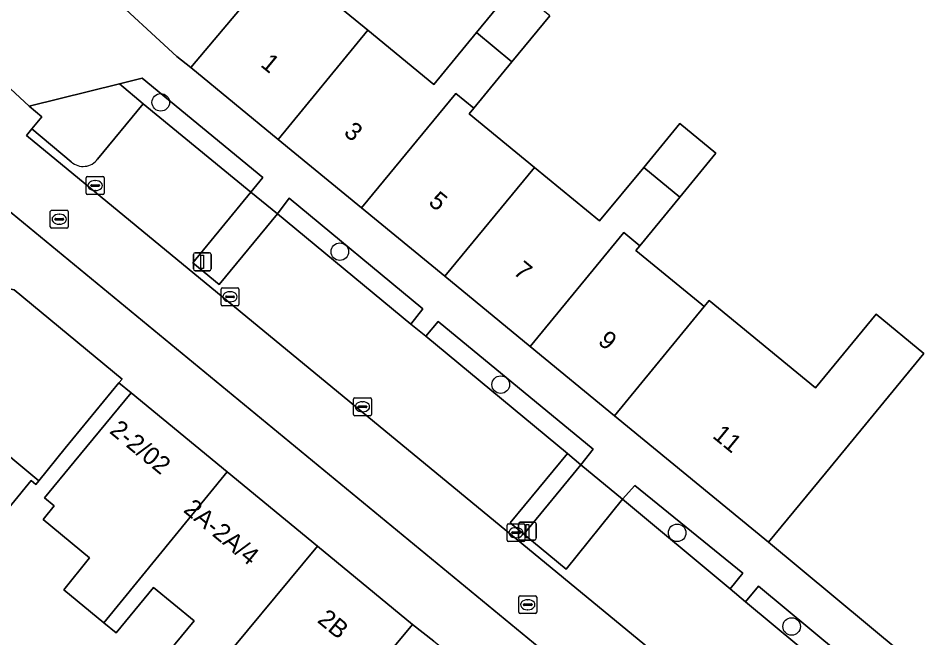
# Model space of a CAD drawing. Extents: x 160157 to 160921, y 381516 to 382045.
# Drawn here: x 160314.8 to 160365.5, y 381930.5 to 381965.1 of the extents above; entities that cross this region are included whole.
import ezdxf

# ---------------------------------------------------------------- set-up
doc = ezdxf.new("R2010")
doc.units = 0
for name, color, linetype in [('IMGEO_Boom', 7, 'Continuous'), ('IMGEO_Erf', 7, 'Continuous'), ('IMGEO_Groenvoorziening', 7, 'Continuous'), ('IMGEO_Haag', 7, 'Continuous'), ('IMGEO_Kolk', 7, 'Continuous'), ('IMGEO_Lichtmast', 7, 'Continuous'), ('IMGEO_Pand', 7, 'Continuous'), ('IMGEO_Pand_nummerreeks', 7, 'Continuous'), ('IMGEO_Parkeervlak_open', 7, 'Continuous'), ('IMGEO_Rijbaan_lokaal_open', 7, 'Continuous'), ('IMGEO_Rioolput', 7, 'Continuous'), ('IMGEO_Voetpad_open', 7, 'Continuous')]:
    doc.layers.add(name, color=color, linetype=linetype)

msp = doc.modelspace()

# ---------------------------------------------------------------- linework, layer by layer
at = {"layer": 'IMGEO_Boom'}
for centre in [(160322.726, 381960.375), (160332.708, 381952.049), (160341.678, 381944.633), (160351.512, 381936.365), (160357.891, 381931.142)]:
    msp.add_circle(centre, 0.489, dxfattribs=at)
at = {"layer": 'IMGEO_Erf'}
for points in [[(160319.596, 381966.674), (160323.63, 381962.943), (160324.402, 381962.313), (160331.716, 381971.016)], [(160331.553, 381966.639), (160334.273, 381964.402), (160337.947, 381961.381), (160340.324, 381964.272), (160342.433, 381966.836)], [(160344.409, 381965.211), (160342.3, 381962.646), (160340.171, 381960.057), (160339.912, 381959.742), (160343.551, 381956.749), (160347.187, 381953.76), (160349.646, 381956.751), (160351.654, 381959.193), (160353.667, 381957.538), (160351.659, 381955.096), (160349.425, 381952.38), (160349.212, 381952.121), (160352.884, 381949.102), (160353.024, 381948.987), (160353.303, 381949.327), (160356.629, 381946.593), (160359.23, 381944.455), (160362.603, 381948.557), (160365.262, 381946.365), (160359.777, 381939.701), (160356.601, 381935.838), (160365.87, 381928.117)], [(160323.177, 381929.746), (160324.583, 381931.452), (160322.328, 381933.31), (160320.241, 381930.777), (160319.551, 381931.345), (160317.331, 381933.175), (160318.753, 381934.963), (160316.167, 381937.112), (160316.789, 381937.866), (160316.242, 381938.317), (160317.893, 381940.32), (160321.073, 381944.178), (160320.396, 381944.729), (160317.394, 381941.086), (160315.932, 381939.263), (160315.768, 381939.058), (160315.504, 381939.276), (160313.335, 381936.645)], [(160337.94, 381930.325), (160336.75, 381931.258), (160333.571, 381927.4)]]:
    msp.add_lwpolyline(points, dxfattribs=at)
at = {"layer": 'IMGEO_Groenvoorziening'}
for points in [[(160321.685, 381961.718), (160320.432, 381961.41), (160321.749, 381960.287), (160327.742, 381955.36), (160328.425, 381956.194)], [(160329.878, 381955.035), (160329.226, 381954.16), (160336.672, 381947.995), (160337.343, 381948.854)], [(160338.181, 381948.144), (160337.502, 381947.343), (160345.394, 381940.788), (160346.146, 381940.163), (160346.828, 381941.024)], [(160349.158, 381939.008), (160348.464, 381938.24), (160354.461, 381933.234), (160355.173, 381934.108)], [(160356.044, 381933.38), (160355.318, 381932.519), (160361.259, 381927.56), (160361.986, 381928.441)]]:
    msp.add_lwpolyline(points, close=True, dxfattribs=at)
for points in [[(160321.749, 381960.287), (160320.432, 381961.41), (160315.4, 381960.173), (160316.098, 381959.567), (160315.541, 381958.892), (160317.74, 381957.054)], [(160319.205, 381957.216), (160321.749, 381960.287)]]:
    msp.add_lwpolyline(points, dxfattribs=at)
msp.add_arc((160318.4, 381957.795), 0.992, 228.3207, 324.2996, dxfattribs=at)
at = {"layer": 'IMGEO_Haag'}
for points in [[(160329.226, 381954.16), (160336.672, 381947.995), (160337.343, 381948.854), (160329.878, 381955.035)], [(160338.181, 381948.144), (160337.502, 381947.343), (160345.394, 381940.788), (160346.146, 381940.163), (160346.828, 381941.024)], [(160354.461, 381933.234), (160355.173, 381934.108), (160349.158, 381939.008), (160348.464, 381938.24)], [(160361.259, 381927.56), (160361.986, 381928.441), (160356.044, 381933.38), (160355.318, 381932.519)]]:
    msp.add_lwpolyline(points, close=True, dxfattribs=at)
at = {"layer": 'IMGEO_Kolk'}
for p, q in [((160318.57, 381955.31), (160318.57, 381956.162)), ((160318.645, 381956.236), (160319.497, 381956.236)), ((160319.058, 381956.016), (160319.083, 381956.016)), ((160319.571, 381956.162), (160319.571, 381955.31)), ((160318.829, 381955.73), (160318.829, 381955.742)), ((160319.267, 381955.693), (160318.869, 381955.693)), ((160318.872, 381955.779), (160319.27, 381955.779)), ((160319.081, 381955.456), (160319.056, 381955.456)), ((160319.313, 381955.742), (160319.313, 381955.73)), ((160319.497, 381955.236), (160318.645, 381955.236)), ((160326.085, 381949.105), (160326.085, 381949.957)), ((160326.16, 381950.031), (160327.012, 381950.031)), ((160327.086, 381949.957), (160327.086, 381949.105)), ((160326.344, 381949.525), (160326.344, 381949.537)), ((160326.782, 381949.488), (160326.384, 381949.488)), ((160326.387, 381949.574), (160326.785, 381949.574)), ((160326.573, 381949.811), (160326.598, 381949.811)), ((160326.828, 381949.537), (160326.828, 381949.525)), ((160327.012, 381949.031), (160326.16, 381949.031)), ((160326.596, 381949.251), (160326.571, 381949.251)), ((160333.468, 381942.971), (160333.468, 381943.823)), ((160333.543, 381943.897), (160334.395, 381943.897)), ((160334.469, 381943.823), (160334.469, 381942.971)), ((160333.727, 381943.391), (160333.727, 381943.403)), ((160334.165, 381943.354), (160333.767, 381943.354)), ((160333.77, 381943.44), (160334.168, 381943.44)), ((160333.956, 381943.677), (160333.981, 381943.677)), ((160334.211, 381943.403), (160334.211, 381943.391)), ((160334.395, 381942.897), (160333.543, 381942.897)), ((160333.979, 381943.117), (160333.954, 381943.117)), ((160342.029, 381935.946), (160342.029, 381936.798)), ((160342.104, 381936.872), (160342.956, 381936.872)), ((160343.03, 381936.798), (160343.03, 381935.946)), ((160342.288, 381936.366), (160342.288, 381936.378)), ((160342.726, 381936.329), (160342.328, 381936.329)), ((160342.331, 381936.415), (160342.729, 381936.415)), ((160342.517, 381936.652), (160342.542, 381936.652)), ((160342.772, 381936.378), (160342.772, 381936.366)), ((160342.956, 381935.872), (160342.104, 381935.872)), ((160342.54, 381936.092), (160342.515, 381936.092))]:
    msp.add_line(p, q, dxfattribs=at)
for points in [[(160318.57, 381955.31), (160318.57, 381956.162)], [(160318.645, 381956.236), (160319.497, 381956.236)], [(160319.571, 381956.162), (160319.571, 381955.31)], [(160319.497, 381955.236), (160318.645, 381955.236)], [(160326.085, 381949.105), (160326.085, 381949.957)], [(160326.16, 381950.031), (160327.012, 381950.031)], [(160327.086, 381949.957), (160327.086, 381949.105)], [(160327.012, 381949.031), (160326.16, 381949.031)], [(160333.468, 381942.971), (160333.468, 381943.823)], [(160333.543, 381943.897), (160334.395, 381943.897)], [(160334.469, 381943.823), (160334.469, 381942.971)], [(160334.395, 381942.897), (160333.543, 381942.897)], [(160342.029, 381935.946), (160342.029, 381936.798)], [(160342.104, 381936.872), (160342.956, 381936.872)], [(160343.03, 381936.798), (160343.03, 381935.946)], [(160342.956, 381935.872), (160342.104, 381935.872)]]:
    msp.add_lwpolyline(points, dxfattribs=at)
for centre, radius, start, end in [((160318.647, 381956.16), 0.0765, 91.552, 178.448), ((160318.647, 381956.16), 0.0765, 91.552, 178.448), ((160319.495, 381956.16), 0.0765, 1.552, 88.448), ((160319.495, 381956.16), 0.0765, 1.552, 88.448), ((160318.869, 381955.739), 0.0403, 85.8775, 175.7526), ((160318.866, 381955.729), 0.0366, 178.938, 274.7102), ((160319.27, 381955.736), 0.043, 264.8664, 352.4533), ((160319.274, 381955.741), 0.0386, 1.7309, 96.639), ((160318.647, 381955.312), 0.0765, 181.552, 268.448), ((160318.647, 381955.312), 0.0765, 181.552, 268.448), ((160319.495, 381955.312), 0.0765, 271.552, 358.448), ((160319.495, 381955.312), 0.0765, 271.552, 358.448), ((160326.162, 381949.955), 0.0765, 91.552, 178.448), ((160326.162, 381949.955), 0.0765, 91.552, 178.448), ((160327.01, 381949.955), 0.0765, 1.552, 88.448), ((160327.01, 381949.955), 0.0765, 1.552, 88.448), ((160326.384, 381949.534), 0.0403, 85.8775, 175.7526), ((160326.381, 381949.524), 0.0366, 178.938, 274.7102), ((160326.785, 381949.531), 0.043, 264.8664, 352.4533), ((160326.789, 381949.536), 0.0386, 1.7309, 96.639), ((160326.162, 381949.107), 0.0765, 181.552, 268.448), ((160326.162, 381949.107), 0.0765, 181.552, 268.448), ((160327.01, 381949.107), 0.0765, 271.552, 358.448), ((160327.01, 381949.107), 0.0765, 271.552, 358.448), ((160333.545, 381943.821), 0.0765, 91.552, 178.448), ((160333.545, 381943.821), 0.0765, 91.552, 178.448), ((160334.393, 381943.821), 0.0765, 1.552, 88.448), ((160334.393, 381943.821), 0.0765, 1.552, 88.448), ((160333.767, 381943.4), 0.0403, 85.8775, 175.7526), ((160333.764, 381943.39), 0.0366, 178.938, 274.7102), ((160334.168, 381943.397), 0.043, 264.8664, 352.4533), ((160334.172, 381943.402), 0.0386, 1.7309, 96.639), ((160333.545, 381942.973), 0.0765, 181.552, 268.448), ((160333.545, 381942.973), 0.0765, 181.552, 268.448), ((160334.393, 381942.973), 0.0765, 271.552, 358.448), ((160334.393, 381942.973), 0.0765, 271.552, 358.448), ((160342.106, 381936.796), 0.0765, 91.552, 178.448), ((160342.106, 381936.796), 0.0765, 91.552, 178.448), ((160342.954, 381936.796), 0.0765, 1.552, 88.448), ((160342.954, 381936.796), 0.0765, 1.552, 88.448), ((160342.328, 381936.375), 0.0403, 85.8775, 175.7526), ((160342.325, 381936.365), 0.0366, 178.938, 274.7102), ((160342.729, 381936.372), 0.043, 264.8664, 352.4533), ((160342.733, 381936.377), 0.0386, 1.7309, 96.639), ((160342.106, 381935.948), 0.0765, 181.552, 268.448), ((160342.106, 381935.948), 0.0765, 181.552, 268.448), ((160342.954, 381935.948), 0.0765, 271.552, 358.448), ((160342.954, 381935.948), 0.0765, 271.552, 358.448)]:
    msp.add_arc(centre, radius, start, end, dxfattribs=at)
for centre, major_axis, ratio, start_param, end_param in [((160319.057, 381955.736), (-0.387, 0.002), 0.722429, 4.712389, 7.853982), ((160319.082, 381955.736), (-0.39, 0.002), 0.717154, 1.570796, 4.712389), ((160326.572, 381949.531), (-0.387, 0.002), 0.722429, 4.712389, 7.853982), ((160326.597, 381949.531), (-0.39, 0.002), 0.717154, 1.570796, 4.712389), ((160333.955, 381943.397), (-0.387, 0.002), 0.722429, 4.712389, 7.853982), ((160333.98, 381943.397), (-0.39, 0.002), 0.717154, 1.570796, 4.712389), ((160342.516, 381936.372), (-0.387, 0.002), 0.722429, 4.712389, 7.853982), ((160342.541, 381936.372), (-0.39, 0.002), 0.717154, 1.570796, 4.712389)]:
    msp.add_ellipse(centre, major_axis=major_axis, ratio=ratio, start_param=start_param, end_param=end_param, dxfattribs=at)
at = {"layer": 'IMGEO_Lichtmast'}
for p, q in [((160324.646, 381951.985), (160325.436, 381951.985)), ((160325.436, 381951.985), (160324.646, 381951.985)), ((160324.546, 381951.085), (160324.546, 381951.885)), ((160324.546, 381951.885), (160324.546, 381951.085)), ((160325.536, 381951.885), (160325.536, 381951.085)), ((160325.536, 381951.085), (160325.536, 381951.885)), ((160325.436, 381950.985), (160324.646, 381950.985)), ((160324.646, 381950.985), (160325.436, 381950.985)), ((160342.67, 381936.059), (160342.67, 381936.859)), ((160342.67, 381936.859), (160342.67, 381936.059)), ((160342.77, 381936.959), (160343.56, 381936.959)), ((160343.56, 381936.959), (160342.77, 381936.959)), ((160343.66, 381936.859), (160343.66, 381936.059)), ((160343.66, 381936.059), (160343.66, 381936.859)), ((160343.56, 381935.959), (160342.77, 381935.959)), ((160342.77, 381935.959), (160343.56, 381935.959))]:
    msp.add_line(p, q, dxfattribs=at)
for points in [[(160324.966, 381951.86), (160325.116, 381951.86), (160325.116, 381951.11), (160324.966, 381951.11), (160324.966, 381951.86)], [(160343.09, 381936.834), (160343.24, 381936.834), (160343.24, 381936.084), (160343.09, 381936.084), (160343.09, 381936.834)]]:
    msp.add_lwpolyline(points, dxfattribs=at)
for centre, start, end in [((160324.646, 381951.885), 90, 180), ((160324.646, 381951.885), 90, 180), ((160325.436, 381951.885), 0, 90), ((160325.436, 381951.885), 360, 90), ((160324.646, 381951.085), 180, 270), ((160324.646, 381951.085), 180, 270), ((160325.436, 381951.085), 270, 0), ((160325.436, 381951.085), 270, 0), ((160342.77, 381936.859), 90, 180), ((160342.77, 381936.859), 90, 180), ((160343.56, 381936.859), 0, 90), ((160343.56, 381936.859), 360, 90), ((160342.77, 381936.059), 180, 270), ((160342.77, 381936.059), 180, 270), ((160343.56, 381936.059), 270, 0), ((160343.56, 381936.059), 270, 0)]:
    msp.add_arc(centre, 0.1, start, end, dxfattribs=at)
at = {"layer": 'IMGEO_Pand'}
for points in [[(160334.273, 381964.402), (160331.553, 381966.639), (160333.766, 381969.33), (160331.716, 381971.016), (160324.402, 381962.313), (160329.267, 381958.313)], [(160340.324, 381964.272), (160342.3, 381962.646), (160344.409, 381965.211), (160342.433, 381966.836)], [(160333.919, 381954.488), (160339.172, 381960.877), (160340.171, 381960.057), (160342.3, 381962.646), (160340.324, 381964.272), (160337.947, 381961.381), (160334.273, 381964.402), (160329.267, 381958.313)], [(160333.919, 381954.488), (160338.557, 381950.675), (160343.551, 381956.749), (160339.912, 381959.742), (160340.171, 381960.057), (160339.172, 381960.877)], [(160349.646, 381956.751), (160351.659, 381955.096), (160353.667, 381957.538), (160351.654, 381959.193)], [(160349.646, 381956.751), (160347.187, 381953.76), (160343.551, 381956.749), (160338.557, 381950.675), (160343.315, 381946.762), (160348.534, 381953.111), (160349.425, 381952.38), (160351.659, 381955.096)], [(160348.017, 381942.896), (160353.024, 381948.987), (160352.884, 381949.102), (160349.212, 381952.121), (160349.425, 381952.38), (160348.534, 381953.111), (160343.315, 381946.762)], [(160314.547, 381949.911), (160303.648, 381952.346), (160302.402, 381952.62), (160300.943, 381945.827), (160310.305, 381943.95), (160315.932, 381939.263), (160317.394, 381941.086), (160320.396, 381944.729), (160320.573, 381944.944)], [(160365.262, 381946.365), (160362.603, 381948.557), (160359.23, 381944.455), (160356.629, 381946.593), (160353.303, 381949.327), (160353.024, 381948.987), (160348.017, 381942.896), (160356.601, 381935.838), (160359.777, 381939.701)], [(160310.305, 381943.95), (160300.943, 381945.827), (160299.997, 381941.422), (160307.388, 381939.979), (160307.525, 381939.949), (160309.331, 381939.549), (160312.439, 381937.379), (160313.335, 381936.645), (160315.504, 381939.276), (160315.768, 381939.058), (160315.932, 381939.263)], [(160326.419, 381939.772), (160321.073, 381944.178), (160317.893, 381940.32), (160316.242, 381938.317), (160316.789, 381937.866), (160316.167, 381937.112), (160318.753, 381934.963), (160317.331, 381933.175), (160319.551, 381931.345)], [(160319.551, 381931.345), (160320.241, 381930.777), (160322.328, 381933.31), (160324.583, 381931.452), (160323.177, 381929.746), (160325.21, 381928.07), (160331.466, 381935.613), (160326.419, 381939.772)], [(160325.21, 381928.07), (160324.13, 381926.642), (160326.295, 381924.858), (160328.82, 381927.88), (160331.909, 381925.366), (160333.571, 381927.4), (160336.75, 381931.258), (160331.466, 381935.613)]]:
    msp.add_lwpolyline(points, close=True, dxfattribs=at)
at = {"layer": 'IMGEO_Parkeervlak_open'}
for points in [[(160337.502, 381947.343), (160336.672, 381947.995), (160329.226, 381954.16), (160325.975, 381950.218), (160324.511, 381951.418), (160327.742, 381955.36), (160321.749, 381960.287), (160319.205, 381957.216)], [(160317.74, 381957.054), (160315.541, 381958.892), (160315.245, 381958.534), (160351.289, 381928.805), (160360.149, 381921.379)], [(160361.321, 381921.094), (160358.101, 381923.793), (160361.259, 381927.56), (160355.318, 381932.519), (160354.461, 381933.234), (160348.464, 381938.24), (160345.331, 381934.336), (160342.956, 381936.295), (160342.202, 381936.917), (160345.394, 381940.788), (160337.502, 381947.343)]]:
    msp.add_lwpolyline(points, dxfattribs=at)
msp.add_arc((160318.4, 381957.795), 0.992, 228.3207, 324.2996, dxfattribs=at)
at = {"layer": 'IMGEO_Rijbaan_lokaal_open'}
msp.add_lwpolyline([(160360.149, 381921.379), (160351.289, 381928.805), (160315.245, 381958.534), (160315.541, 381958.892), (160316.098, 381959.567), (160315.4, 381960.173), (160312.536, 381962.804), (160309.064, 381958.612), (160359.924, 381916.684), (160369.605, 381914.849), (160369.748, 381915.384)], dxfattribs=at)
at = {"layer": 'IMGEO_Rioolput'}
for p, q in [((160316.569, 381953.431), (160316.569, 381954.283)), ((160316.644, 381954.357), (160317.496, 381954.357)), ((160317.057, 381954.137), (160317.082, 381954.137)), ((160317.57, 381954.283), (160317.57, 381953.431)), ((160316.828, 381953.851), (160316.828, 381953.863)), ((160317.266, 381953.814), (160316.868, 381953.814)), ((160316.871, 381953.9), (160317.269, 381953.9)), ((160317.08, 381953.577), (160317.055, 381953.577)), ((160317.312, 381953.863), (160317.312, 381953.851)), ((160317.496, 381953.357), (160316.644, 381953.357)), ((160342.682, 381931.929), (160342.682, 381932.781)), ((160342.757, 381932.855), (160343.609, 381932.855)), ((160343.17, 381932.635), (160343.195, 381932.635)), ((160343.683, 381932.781), (160343.683, 381931.929)), ((160342.941, 381932.349), (160342.941, 381932.361)), ((160343.379, 381932.312), (160342.981, 381932.312)), ((160342.984, 381932.398), (160343.382, 381932.398)), ((160343.425, 381932.361), (160343.425, 381932.349)), ((160343.609, 381931.855), (160342.757, 381931.855)), ((160343.193, 381932.075), (160343.168, 381932.075))]:
    msp.add_line(p, q, dxfattribs=at)
for points in [[(160316.569, 381953.431), (160316.569, 381954.283)], [(160316.644, 381954.357), (160317.496, 381954.357)], [(160317.57, 381954.283), (160317.57, 381953.431)], [(160317.496, 381953.357), (160316.644, 381953.357)], [(160342.682, 381931.929), (160342.682, 381932.781)], [(160342.757, 381932.855), (160343.609, 381932.855)], [(160343.683, 381932.781), (160343.683, 381931.929)], [(160343.609, 381931.855), (160342.757, 381931.855)]]:
    msp.add_lwpolyline(points, dxfattribs=at)
for centre, radius, start, end in [((160316.646, 381954.281), 0.0765, 91.552, 178.448), ((160316.646, 381954.281), 0.0765, 91.552, 178.448), ((160317.494, 381954.281), 0.0765, 1.552, 88.448), ((160317.494, 381954.281), 0.0765, 1.552, 88.448), ((160316.646, 381953.433), 0.0765, 181.552, 268.448), ((160316.646, 381953.433), 0.0765, 181.552, 268.448), ((160316.868, 381953.86), 0.0403, 85.8775, 175.7526), ((160316.865, 381953.85), 0.0366, 178.938, 274.7102), ((160317.269, 381953.857), 0.043, 264.8664, 352.4533), ((160317.273, 381953.862), 0.0386, 1.7309, 96.639), ((160317.494, 381953.433), 0.0765, 271.552, 358.448), ((160317.494, 381953.433), 0.0765, 271.552, 358.448), ((160342.759, 381932.779), 0.0765, 91.552, 178.448), ((160342.759, 381932.779), 0.0765, 91.552, 178.448), ((160343.607, 381932.779), 0.0765, 1.552, 88.448), ((160343.607, 381932.779), 0.0765, 1.552, 88.448), ((160342.981, 381932.358), 0.0403, 85.8775, 175.7526), ((160342.978, 381932.348), 0.0366, 178.938, 274.7102), ((160343.382, 381932.355), 0.043, 264.8664, 352.4533), ((160343.386, 381932.36), 0.0386, 1.7309, 96.639), ((160342.759, 381931.931), 0.0765, 181.552, 268.448), ((160342.759, 381931.931), 0.0765, 181.552, 268.448), ((160343.607, 381931.931), 0.0765, 271.552, 358.448), ((160343.607, 381931.931), 0.0765, 271.552, 358.448)]:
    msp.add_arc(centre, radius, start, end, dxfattribs=at)
for centre, major_axis, ratio, start_param, end_param in [((160317.056, 381953.857), (-0.387, 0.002), 0.722429, 4.712389, 7.853982), ((160317.081, 381953.857), (-0.39, 0.002), 0.717154, 1.570796, 4.712389), ((160343.169, 381932.355), (-0.387, 0.002), 0.722429, 4.712389, 7.853982), ((160343.194, 381932.355), (-0.39, 0.002), 0.717154, 1.570796, 4.712389)]:
    msp.add_ellipse(centre, major_axis=major_axis, ratio=ratio, start_param=start_param, end_param=end_param, dxfattribs=at)
at = {"layer": 'IMGEO_Voetpad_open'}
for points in [[(160417.865, 381885.448), (160409.913, 381891.762), (160405.98, 381895.008), (160402.178, 381898.146), (160398.377, 381901.283), (160394.442, 381904.531), (160393.686, 381905.155), (160389.982, 381908.211), (160386.102, 381911.413), (160382.063, 381914.747), (160381.302, 381915.381), (160377.373, 381918.624), (160373.586, 381921.749), (160369.799, 381924.874), (160365.87, 381928.117), (160356.601, 381935.838), (160348.017, 381942.896), (160343.315, 381946.762), (160338.557, 381950.675), (160333.919, 381954.488), (160329.267, 381958.313), (160324.402, 381962.313), (160323.63, 381962.943), (160319.596, 381966.674)], [(160312.536, 381962.804), (160315.4, 381960.173), (160320.432, 381961.41), (160321.685, 381961.718), (160328.425, 381956.194), (160327.742, 381955.36), (160329.226, 381954.16), (160329.878, 381955.035), (160337.343, 381948.854), (160336.672, 381947.995), (160337.502, 381947.343), (160338.181, 381948.144), (160346.828, 381941.024), (160346.146, 381940.163), (160348.464, 381938.24), (160349.158, 381939.008), (160355.173, 381934.108), (160354.461, 381933.234), (160355.318, 381932.519), (160356.044, 381933.38), (160361.986, 381928.441), (160361.259, 381927.56), (160363.739, 381925.575), (160361.243, 381922.685)], [(160304.159, 381960.798), (160302.654, 381953.794), (160302.402, 381952.62), (160303.648, 381952.346), (160314.547, 381949.911), (160320.573, 381944.944), (160320.396, 381944.729), (160321.073, 381944.178), (160326.419, 381939.772), (160331.466, 381935.613), (160336.75, 381931.258), (160337.94, 381930.325), (160340.102, 381928.629), (160344.499, 381924.996), (160348.857, 381921.395), (160349.638, 381920.772), (160353.572, 381917.522), (160357.461, 381914.308), (160358.404, 381913.522), (160362.436, 381910.191), (160366.268, 381907.024)], [(160369.605, 381914.849), (160359.924, 381916.684), (160309.064, 381958.612), (160308.058, 381959.424)]]:
    msp.add_lwpolyline(points, dxfattribs=at)
for points in [[(160329.226, 381954.16), (160327.742, 381955.36), (160324.511, 381951.418), (160325.975, 381950.218)], [(160346.146, 381940.163), (160345.394, 381940.788), (160342.202, 381936.917), (160342.956, 381936.295)], [(160348.464, 381938.24), (160346.146, 381940.163), (160342.956, 381936.295), (160345.331, 381934.336)]]:
    msp.add_lwpolyline(points, close=True, dxfattribs=at)

# ---------------------------------------------------------------- texts
at = {"layer": 'IMGEO_Pand_nummerreeks'}
for s, rotation, p in [('1', 320.5733, (160328.239, 381962.42)), ('3', 320.5733, (160332.874, 381958.609)), ('5', 320.5733, (160337.597, 381954.726)), ('7', 320.5733, (160342.32, 381950.843)), ('9', 320.5733, (160347.043, 381946.96)), ('2-2/02', 320.506, (160319.818, 381941.973)), ('11', 320.569, (160353.43, 381941.708)), ('2A-2A/4', 320.5096, (160323.937, 381937.567)), ('2B', 320.5051, (160331.402, 381931.417))]:
    msp.add_text(s, height=1, rotation=rotation, dxfattribs=at).set_placement(p)

doc.saveas('drawing.dxf')
